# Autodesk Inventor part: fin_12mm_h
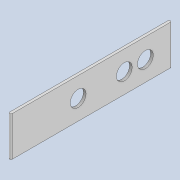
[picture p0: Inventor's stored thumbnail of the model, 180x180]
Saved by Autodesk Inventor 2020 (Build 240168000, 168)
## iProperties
Created: 2021-10
Part Number: fin_12mm_h
Material: Generic
Document SubType Name: Modeling
Designer: Shuang Peng
Density: 1 g/cm^3
Appearance: Default
Author: Shuang Peng
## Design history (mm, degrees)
sketch "Sketch1"
  geometry: L1 (0, 0)-(0, -12); L2 (-0.1, 0)-(-0.1, -12); L3 (0.1, -12)-(0.1, 0); A1 r 0.1 centre (0, 0) between (0.1, 0) and (-0.1, 0); A2 r 0.1 centre (0, -12) between (-0.1, -12) and (0.1, -12); 1 further point
  constraints: 8 end point, 4 point on circle, 4 tangent, 2 centre point, 1 midpoint, 1 parallel, 1 vertical
  dimensions: "d0" = 12 distance of L1.start L1.end; "d1" = 0.2 diameter of A2
extrude "Extrusion1" new body sketch "Sketch1" distance "d2" = 3; taper "d3" = 0 deg
sketch "Sketch2"
  geometry: L1 (12.1, 0)-(12.1, 3) reference; L2 (12.1, 1.5)-(10.1, 1.5); C1 r 0.6 at (10.1, 1.5); 1 further point
  constraints: 2 end point, 1 centre point, 1 coincident, 1 horizontal, 1 midpoint
  dimensions: "d4" = 2 distance of L2.start L2.end; "d5" = 1.2 diameter of C1
extrude "Extrusion2" cut sketch "Sketch2" distance "d6" = 3; taper "d7" = 0 deg
sketch "Sketch3"
  geometry: L1 (0, 0)-(0, 3) reference; L2 (0, 1.5)-(5, 1.5); L3 (5, 1.5)-(8.5, 1.5); C1 r 0.6 at (5, 1.5); C2 r 0.6 at (8.5, 1.5)
  constraints: 4 end point, 2 centre point, 2 coincident, 1 collinear, 1 horizontal, 1 midpoint
  dimensions: "d8" = 5 distance of L2.start L2.end; "d9" = 3.5 distance of L2.end L3.end; "d10" = 1.2 diameter of C1; "d11" = 1.2 diameter of C2
extrude "Extrusion3" cut sketch "Sketch3" distance "d12" = 10; taper "d13" = 0 deg
body "Solid1"
